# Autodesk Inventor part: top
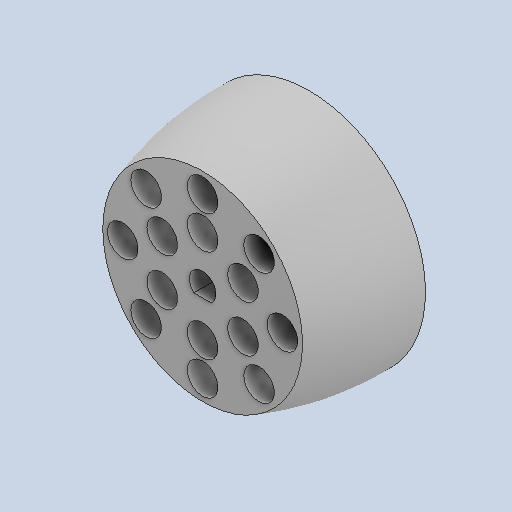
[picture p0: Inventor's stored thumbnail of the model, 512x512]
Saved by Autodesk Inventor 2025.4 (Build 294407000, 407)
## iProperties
Created: 2026-09
Part Number: top
Material: Generic
Document SubType Name: Modeling
Designer: AdminForWorker
Density: 1 g/cm^3
Appearance: Default
Title: top
Author: AdminForWorker
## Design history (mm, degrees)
feature "Body1"
body "Solid1"
